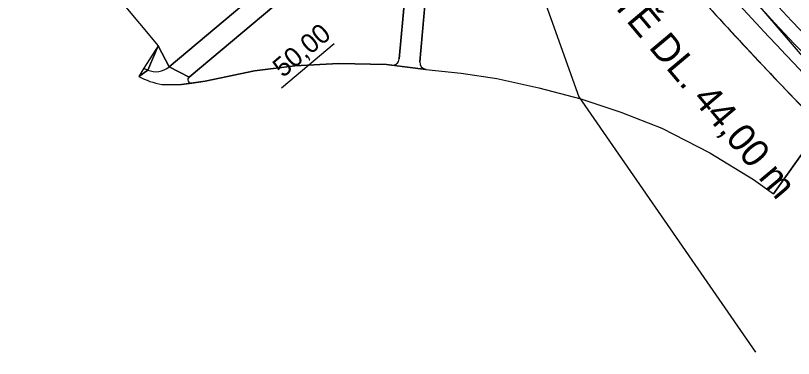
# Model space of a CAD drawing. Extents: x -606444 to -604546, y -1158114 to -1156869.
# Drawn here: x -605127.5 to -605014.7, y -1157503.1 to -1157453.4 of the extents above; entities that cross this region are included whole.
import ezdxf

# ---------------------------------------------------------------- set-up
doc = ezdxf.new("R2010")
doc.units = 0
for name, color, linetype in [('B_CHOD', 7, 'Continuous'), ('B_TRAM', 7, 'Continuous'), ('B_ZELEN', 7, 'Continuous'), ('geofyzikální profily_předběžný GTP', 7, 'Continuous'), ('NS_VB', 7, 'Continuous'), ('NS_VB_POP', 7, 'Continuous'), ('OSA', 7, 'Continuous'), ('OSAPOP', 7, 'Continuous'), ('podélný profil trasou tramvaje', 7, 'Continuous')]:
    doc.layers.add(name, color=color, linetype=linetype)

msp = doc.modelspace()

# ---------------------------------------------------------------- linework, layer by layer
at = {"layer": 'B_CHOD'}
for points in [[(-605074.52, -1157435), (-605105.21, -1157460.82), (-605102.31, -1157462.3), (-605071.49, -1157436.38), (-605074.52, -1157435)], [(-605068.88, -1157460.1), (-605066.69, -1157435.55), (-605069.85, -1157437.23), (-605071.85, -1157459.66)], [(-605108.86, -1157461.03), (-605109.61, -1157462.21), (-605108.31, -1157461.28)], [(-605102.31, -1157462.3), (-605105.21, -1157460.82)], [(-605072.94, -1157460.57), (-605068.02, -1157461.18)], [(-605108.31, -1157461.28), (-605108.31, -1157461.28), (-605109.61, -1157462.21), (-605109.62, -1157462.24)], [(-605106.29, -1157463.4), (-605103.42, -1157463.39), (-605101.92, -1157463.18)], [(-605101.92, -1157463.18), (-605101.92, -1157463.18)]]:
    msp.add_lwpolyline(points, dxfattribs=at)
for centre, radius, start, end in [((-605072.85, -1157459.58), 1, 264.8698, 354.9079), ((-605103.34, -1157449.57), 12.72, 244.305, 246.9989), ((-605107.14, -1157458.52), 3, 246.9989, 310.0661), ((-605067.88, -1157460.18), 1, 174.9079, 262.1477), ((-605103.34, -1157449.57), 14.14, 243.6154, 257.9538), ((-605101.99, -1157462.68), 0.5, 130.0661, 278.1064), ((-605101.99, -1157462.68), 0.5, 278.1064, 278.1068)]:
    msp.add_arc(centre, radius, start, end, dxfattribs=at)
at = {"layer": 'B_TRAM'}
for radius in [594.5, 605.5]:
    msp.add_arc((-604578.51, -1157045.35), radius, 222.04255, 233.60158, dxfattribs=at)
at = {"layer": 'B_ZELEN'}
for p, q in [((-605066.69, -1157435.55), (-605068.88, -1157460.1)), ((-605071.49, -1157436.38), (-605102.31, -1157462.3)), ((-605071.85, -1157459.66), (-605069.85, -1157437.23)), ((-605092.83, -1157461.42), (-605086.98, -1157460.68)), ((-605086.98, -1157460.68), (-605080.63, -1157460.32)), ((-605080.63, -1157460.32), (-605073.69, -1157460.48)), ((-605099.98, -1157462.9), (-605092.83, -1157461.42)), ((-605068.02, -1157461.18), (-605067.99, -1157461.18)), ((-605067.99, -1157461.18), (-605062.86, -1157461.73)), ((-605062.86, -1157461.73), (-605057.72, -1157462.5)), ((-605101.92, -1157463.18), (-605099.98, -1157462.9)), ((-605057.72, -1157462.5), (-605051.6, -1157463.84)), ((-605051.6, -1157463.84), (-605045.55, -1157465.47)), ((-605045.55, -1157465.47), (-605039.74, -1157467.4)), ((-605039.74, -1157467.4), (-605033.77, -1157469.74)), ((-605033.77, -1157469.74), (-605026.81, -1157473.31)), ((-605017.61, -1157479.23), (-605012.23, -1157471.69)), ((-605026.81, -1157473.31), (-605020.5, -1157477.17)), ((-605020.5, -1157477.17), (-605017.61, -1157479.23))]:
    msp.add_line(p, q, dxfattribs=at)
for points in [[(-605112.2, -1157451.29), (-605106.78, -1157457.79), (-605105.21, -1157460.82), (-605074.52, -1157435), (-605075.12, -1157433.24), (-605127.07, -1157431.03), (-605127.04, -1157431.1), (-605124.61, -1157437.06), (-605123.94, -1157436.79), (-605121.79, -1157435.88), (-605120.08, -1157439.98), (-605118.85, -1157439.46), (-605117.89, -1157441.73), (-605119.1, -1157442.21), (-605117, -1157447.24), (-605115.76, -1157446.7), (-605114.03, -1157450.62), (-605113.26, -1157451.92), (-605112.2, -1157451.29)], [(-605108.31, -1157461.28), (-605108.31, -1157461.28), (-605106.78, -1157457.79), (-605108.86, -1157461.03)], [(-605105.21, -1157460.82), (-605106.78, -1157457.79), (-605108.31, -1157461.28)], [(-605073.69, -1157460.48), (-605072.97, -1157460.57), (-605072.94, -1157460.57)]]:
    msp.add_lwpolyline(points, dxfattribs=at)
for centre, radius, start, end in [((-604578.51, -1157045.35), 594.5, 222.04255, 223.59935), ((-604578.51, -1157045.35), 605.5, 222.04255, 224.55107), ((-605072.85, -1157459.58), 1, 264.8698, 354.9079), ((-605103.34, -1157449.57), 12.72, 244.305, 246.9989), ((-605107.14, -1157458.52), 3, 246.9989, 310.0661), ((-605067.88, -1157460.18), 1, 174.9079, 262.1477), ((-605101.99, -1157462.68), 0.5, 130.0661, 278.1068)]:
    msp.add_arc(centre, radius, start, end, dxfattribs=at)
at = {"layer": 'geofyzikální profily_předběžný GTP'}
msp.add_lwpolyline([(-605668.89, -1157175.56), (-605638.05, -1157172.71), (-605616.09, -1157172.84), (-605512.92, -1157173.16), (-605468.49, -1157175.65), (-605413.5, -1157174.06), (-605313.44, -1157169.44), (-605274.57, -1157178.01), (-605221.39, -1157204.27), (-605178.57, -1157224), (-605160.32, -1157243.28), (-605143.64, -1157289.5), (-605117.17, -1157349.93), (-605096.21, -1157389.16), (-605065.9, -1157426.81), (-605053.52, -1157443.58), (-605045.82, -1157465.15), (-605020.21, -1157502.2)], dxfattribs=at)
at = {"layer": 'NS_VB'}
for p, q in [((-605074.52, -1157435), (-605105.21, -1157460.82)), ((-605066.69, -1157435.55), (-605068.88, -1157460.1)), ((-605071.49, -1157436.38), (-605102.31, -1157462.3)), ((-605069.85, -1157437.23), (-605071.85, -1157459.66)), ((-605112.2, -1157451.29), (-605106.78, -1157457.79)), ((-605106.78, -1157457.79), (-605108.86, -1157461.03)), ((-605108.86, -1157461.03), (-605109.61, -1157462.21)), ((-605086.98, -1157460.68), (-605092.83, -1157461.42)), ((-605080.63, -1157460.32), (-605086.98, -1157460.68)), ((-605073.69, -1157460.48), (-605080.63, -1157460.32)), ((-605067.99, -1157461.18), (-605073.69, -1157460.48)), ((-605109.61, -1157462.21), (-605109.62, -1157462.24)), ((-605092.83, -1157461.42), (-605099.98, -1157462.9)), ((-605067.99, -1157461.18), (-605062.86, -1157461.73)), ((-605062.86, -1157461.73), (-605057.72, -1157462.5)), ((-605106.29, -1157463.4), (-605103.42, -1157463.39)), ((-605099.98, -1157462.9), (-605103.42, -1157463.39)), ((-605057.72, -1157462.5), (-605051.6, -1157463.84)), ((-605051.6, -1157463.84), (-605045.55, -1157465.47)), ((-605045.55, -1157465.47), (-605039.74, -1157467.4)), ((-605039.74, -1157467.4), (-605033.77, -1157469.74)), ((-605033.77, -1157469.74), (-605026.81, -1157473.31)), ((-605012.23, -1157471.69), (-605017.61, -1157479.23)), ((-605026.81, -1157473.31), (-605020.5, -1157477.17)), ((-605020.5, -1157477.17), (-605017.61, -1157479.23))]:
    msp.add_line(p, q, dxfattribs=at)
for centre, radius, start, end in [((-604578.51, -1157045.35), 594.5, 222.04255, 233.60156), ((-604578.51, -1157045.35), 605.5, 222.04255, 233.60156), ((-605072.85, -1157459.58), 1, 262.9669, 354.9079), ((-605103.34, -1157449.57), 12.72, 244.305, 246.9989), ((-605107.14, -1157458.52), 3, 246.9989, 310.0661), ((-605067.88, -1157460.18), 1, 174.9079, 263.8695), ((-605103.34, -1157449.57), 14.14, 243.6154, 257.9538), ((-605101.99, -1157462.68), 0.5, 130.0661, 278.1068)]:
    msp.add_arc(centre, radius, start, end, dxfattribs=at)
at = {"layer": 'OSA'}
for centre, radius, start, end in [((-604578.51, -1157045.35), 600, 221.02098, 233.60156), ((-604578.51, -1157045.35), 602, 221.02094, 226.47692), ((-604591.87, -1157057.41), 580, 222.06105, 233.72643)]:
    msp.add_arc(centre, radius, start, end, dxfattribs=at)
at = {"layer": 'OSAPOP'}
msp.add_line((-605088.94, -1157463.88), (-605081.29, -1157457.44), dxfattribs=at)
at = {"layer": 'podélný profil trasou tramvaje'}
msp.add_lwpolyline([(-604973.89, -1157496.65), (-605009.52, -1157463.78), (-605083.89, -1157377.09), (-605085.67, -1157373.96), (-605102.48, -1157348.99)], dxfattribs=at)

# ---------------------------------------------------------------- texts
at = {"layer": 'NS_VB_POP'}
for p in [(-605040.44, -1157413.36), (-605058.37, -1157431.17)]:
    msp.add_text('NÁSTUPIŠTĚ DL. 44,00 m', height=4, rotation=310.0661, dxfattribs=at).set_placement(p)
at = {"layer": 'OSAPOP'}
msp.add_text('50,00', height=2.8, rotation=40.0733, dxfattribs=at).set_placement((-605088.71, -1157462.47))

doc.saveas('drawing.dxf')
